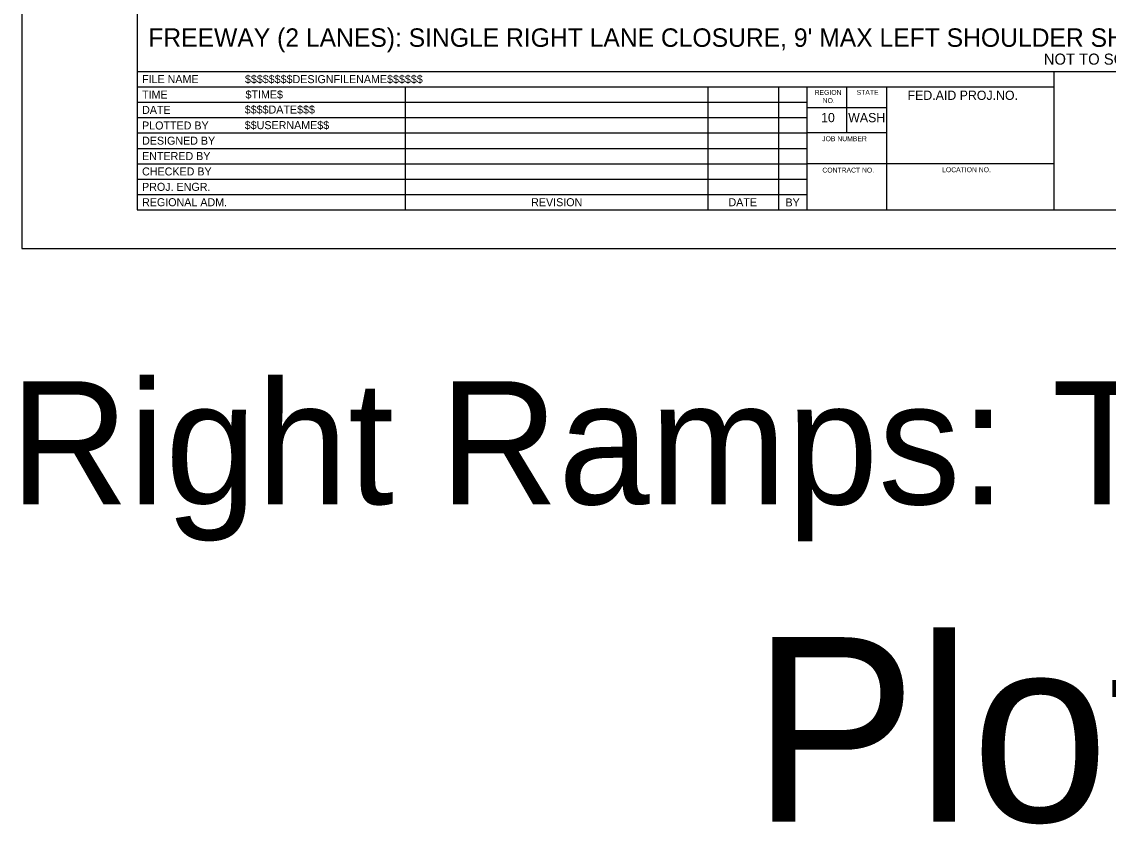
# Model space of a CAD drawing. Extents: x 99999 to 100116, y 99995 to 100013.
# Drawn here: x 100059.06 to 100067.9, y 99995.01 to 100001.53 of the extents above; entities that cross this region are included whole.
import ezdxf

# ---------------------------------------------------------------- set-up
doc = ezdxf.new("R2010")
doc.units = 0
for name, color, linetype in [('SH_DE_DetailHeading1Text', 7, 'Continuous'), ('SH_GI_PlotLimits', 7, 'Continuous'), ('SH_GI_SheetBorder', 7, 'Continuous'), ('SH_GI_SheetLocationText', 7, 'Continuous'), ('SH_GI_SheetTextInCells', 7, 'Continuous'), ('SH_GI_TitleBlockText', 7, 'Continuous')]:
    doc.layers.add(name, color=color, linetype=linetype)

msp = doc.modelspace()

# ---------------------------------------------------------------- linework, layer by layer
at = {"layer": 'SH_GI_PlotLimits'}
msp.add_lwpolyline([(100059.0625, 99999.6875), (100076.0625, 99999.6875), (100076.0625, 100010.6875), (100059.0625, 100010.6875)], close=True, dxfattribs=at)
at = {"layer": 'SH_GI_SheetBorder'}
for p, q in [((100060, 100010.375), (100060, 100000)), ((100060, 100001.1259), (100075.75, 100001.1259)), ((100067.4566, 100000), (100067.4566, 100001.1259)), ((100060, 100001.0008), (100067.4566, 100001.0008)), ((100062.179, 100001.0008), (100062.179, 100000)), ((100064.641, 100001.0008), (100064.641, 100000)), ((100065.2164, 100001.0008), (100065.2164, 100000)), ((100065.4451, 100001.0008), (100065.4451, 100000)), ((100065.7719, 100000.6255), (100065.7719, 100001.0008)), ((100066.0956, 100000), (100066.0956, 100001.0008)), ((100060, 100000.8757), (100062.1821, 100000.8757)), ((100062.1821, 100000.8757), (100065.4466, 100000.8757)), ((100060, 100000.7506), (100062.1821, 100000.7506)), ((100062.1821, 100000.7506), (100065.4466, 100000.7506)), ((100066.0958, 100000.831), (100065.4466, 100000.831)), ((100060, 100000.6255), (100065.4466, 100000.6255)), ((100066.0958, 100000.6255), (100065.4466, 100000.6255)), ((100060, 100000.5004), (100065.4466, 100000.5004)), ((100060, 100000.3753), (100065.4466, 100000.3753)), ((100067.4566, 100000.3753), (100065.4466, 100000.3753)), ((100060, 100000.2502), (100065.4466, 100000.2502)), ((100060, 100000.1251), (100065.4466, 100000.1251)), ((100060, 100000), (100075.75, 100000))]:
    msp.add_line(p, q, dxfattribs=at)

# ---------------------------------------------------------------- texts
at = {"layer": 'SH_DE_DetailHeading1Text'}
for s, height, p in [("FREEWAY (2 LANES): SINGLE RIGHT LANE CLOSURE, 9' MAX LEFT SHOULDER SHIFT (55 MPH WORK ZONE SPEED LIMIT, 40 MPH ADVISORY SPEED)", 0.15, (100060.0913, 100001.3259)), ('NOT TO SCALE', 0.09, (100067.3727, 100001.1809))]:
    msp.add_text(s, height=height, rotation=360, dxfattribs=at).set_placement(p)
at = {"layer": 'SH_GI_SheetLocationText'}
for s, height, p in [('Right Ramps: Tapered On-Ramp', 1, (100058.9666, 99997.6071)), ('Plot 4', 1.5, (100065.0007, 99995.0267))]:
    msp.add_text(s, height=height, dxfattribs=at).set_placement(p)
at = {"layer": 'SH_GI_SheetTextInCells'}
for s, height, p in [('FILE NAME', 0.06505, (100060.041, 100001.0308)), ('TIME', 0.06505, (100060.041, 100000.9057)), ('REGION', 0.04003, (100065.5099, 100000.9352)), ('STATE', 0.04003, (100065.8511, 100000.9357)), ('FED.AID PROJ.NO.', 0.07506, (100066.2652, 100000.8945)), ('DATE', 0.06505, (100060.041, 100000.7806)), ('NO.', 0.04003, (100065.5752, 100000.869)), ('10', 0.07506, (100065.5621, 100000.7131)), ('WASH', 0.07506, (100065.7826, 100000.7131)), ('PLOTTED BY', 0.06505, (100060.041, 100000.6538)), ('DESIGNED BY', 0.065052, (100060.041, 100000.5304)), ('JOB NUMBER', 0.04003, (100065.5712, 100000.5587)), ('ENTERED BY', 0.06505, (100060.041, 100000.4053)), ('CHECKED BY', 0.06505, (100060.041, 100000.2802)), ('CONTRACT NO.', 0.040032, (100065.5725, 100000.3037)), ('LOCATION NO.', 0.040032, (100066.5465, 100000.3067)), ('PROJ. ENGR.', 0.065052, (100060.041, 100000.1551)), ('REGIONAL ADM.', 0.065052, (100060.041, 100000.03)), ('REVISION', 0.06505, (100063.2048, 100000.03)), ('DATE', 0.06505, (100064.8091, 100000.03)), ('BY', 0.06505, (100065.2725, 100000.0285))]:
    msp.add_text(s, height=height, dxfattribs=at).set_placement(p)
at = {"layer": 'SH_GI_TitleBlockText'}
for s, height, p in [('$$$$$$$$DESIGNFILENAME$$$$$$', 0.065052, (100060.8775, 100001.0308)), ('$TIME$', 0.06505, (100060.882, 100000.9059)), ('$$$$DATE$$$', 0.065052, (100060.8759, 100000.7835)), ('$$USERNAME$$', 0.065052, (100060.8759, 100000.6567))]:
    msp.add_text(s, height=height, dxfattribs=at).set_placement(p)

doc.saveas('drawing.dxf')
